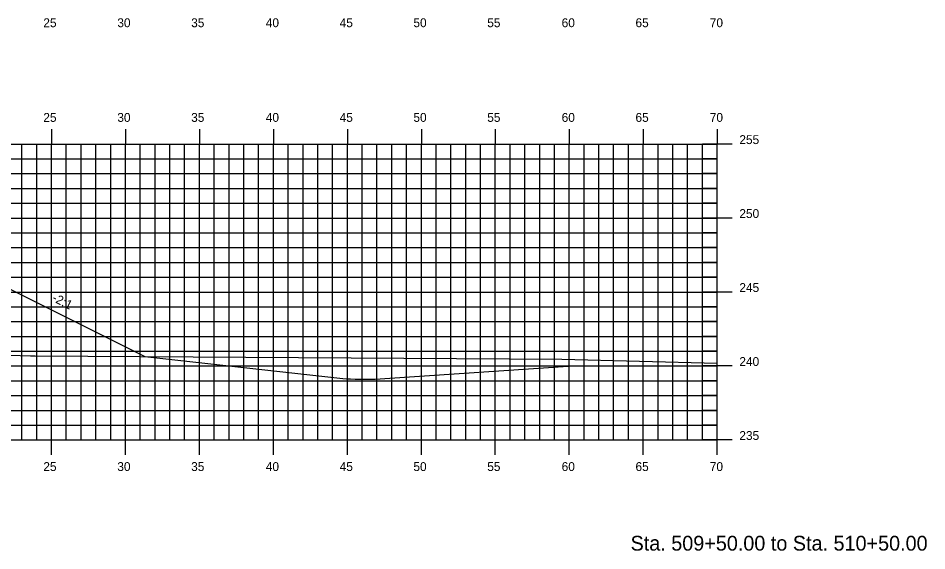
# Model space of a CAD drawing. Extents: x 1170543 to 1177585, y 609599 to 610623.
# Drawn here: x 1172423.3 to 1172484.7, y 610270.3 to 610306.3 of the extents above; entities that cross this region are included whole.
import ezdxf

# ---------------------------------------------------------------- set-up
doc = ezdxf.new("R2010")
doc.units = 0
for name, color, linetype in [('ANNOTATION', 7, 'Continuous'), ('D_Roadway_Centerline', 7, 'Continuous'), ('D_Roadway_Edge_Pavement', 7, 'Continuous'), ('H_V ANNOTATION', 7, 'Continuous'), ('MAJOR', 7, 'Continuous'), ('MINOR', 7, 'Continuous'), ('S_Roadway_Centerline', 7, 'Continuous')]:
    doc.layers.add(name, color=color, linetype=linetype)

msp = doc.modelspace()

# ---------------------------------------------------------------- linework, layer by layer
at = {"layer": 'D_Roadway_Centerline'}
msp.add_lwpolyline([(1172382.176, 610291.056), (1172386.743, 610290.875), (1172387.337, 610290.851), (1172390.392, 610290.731), (1172390.428, 610290.729), (1172395.154, 610290.546), (1172395.785, 610290.521), (1172408.22, 610290.035), (1172416.521, 610289.722), (1172416.521, 610289.722), (1172419.505, 610289.607), (1172423.005, 610287.857), (1172423.005, 610287.857), (1172431.831, 610283.444)], dxfattribs=at)
at = {"layer": 'D_Roadway_Edge_Pavement'}
msp.add_lwpolyline([(1172431.831, 610283.444), (1172445.213, 610281.963), (1172445.459, 610281.94), (1172445.737, 610281.922), (1172446.043, 610281.909), (1172446.372, 610281.903), (1172446.711, 610281.902), (1172447.056, 610281.907), (1172447.399, 610281.917), (1172447.731, 610281.932), (1172448.047, 610281.951), (1172460.788, 610282.801)], dxfattribs=at)
at = {"layer": 'MAJOR'}
for p, q in [((1172425.524, 610298.803), (1172425.524, 610297.801)), ((1172430.524, 610298.803), (1172430.524, 610297.801)), ((1172435.524, 610298.803), (1172435.524, 610297.801)), ((1172440.524, 610298.803), (1172440.524, 610297.801)), ((1172445.524, 610298.803), (1172445.524, 610297.801)), ((1172450.524, 610298.803), (1172450.524, 610297.801)), ((1172455.524, 610298.803), (1172455.524, 610297.801)), ((1172460.524, 610298.803), (1172460.524, 610297.801)), ((1172465.524, 610298.803), (1172465.524, 610297.801)), ((1172470.524, 610298.803), (1172470.524, 610297.801)), ((1172330.524, 610297.801), (1172470.524, 610297.801)), ((1172330.524, 610297.801), (1172470.524, 610297.801)), ((1172425.524, 610277.801), (1172425.524, 610297.801)), ((1172430.524, 610277.801), (1172430.524, 610297.801)), ((1172435.524, 610277.801), (1172435.524, 610297.801)), ((1172440.524, 610277.801), (1172440.524, 610297.801)), ((1172445.524, 610277.801), (1172445.524, 610297.801)), ((1172450.524, 610277.801), (1172450.524, 610297.801)), ((1172455.524, 610277.801), (1172455.524, 610297.801)), ((1172460.524, 610277.801), (1172460.524, 610297.801)), ((1172465.524, 610277.801), (1172465.524, 610297.801)), ((1172471.526, 610297.801), (1172469.522, 610297.801)), ((1172470.524, 610277.801), (1172470.524, 610297.801)), ((1172470.524, 610277.801), (1172470.524, 610297.801)), ((1172330.524, 610292.801), (1172470.524, 610292.801)), ((1172471.526, 610292.801), (1172469.522, 610292.801)), ((1172330.524, 610287.801), (1172470.524, 610287.801)), ((1172471.526, 610287.801), (1172469.522, 610287.801)), ((1172330.524, 610282.801), (1172470.524, 610282.801)), ((1172471.526, 610282.801), (1172469.522, 610282.801)), ((1172330.524, 610277.801), (1172470.524, 610277.801)), ((1172330.524, 610277.801), (1172470.524, 610277.801)), ((1172425.524, 610276.799), (1172425.524, 610277.801)), ((1172430.524, 610276.799), (1172430.524, 610277.801)), ((1172435.524, 610276.799), (1172435.524, 610277.801)), ((1172440.524, 610276.799), (1172440.524, 610277.801)), ((1172445.524, 610276.799), (1172445.524, 610277.801)), ((1172450.524, 610276.799), (1172450.524, 610277.801)), ((1172455.524, 610276.799), (1172455.524, 610277.801)), ((1172460.524, 610276.799), (1172460.524, 610277.801)), ((1172465.524, 610276.799), (1172465.524, 610277.801)), ((1172471.526, 610277.801), (1172469.522, 610277.801)), ((1172470.524, 610276.799), (1172470.524, 610277.801))]:
    msp.add_line(p, q, dxfattribs=at)
at = {"layer": 'MINOR'}
for p, q in [((1172423.524, 610277.801), (1172423.524, 610297.801)), ((1172424.524, 610277.801), (1172424.524, 610297.801)), ((1172426.524, 610277.801), (1172426.524, 610297.801)), ((1172427.524, 610277.801), (1172427.524, 610297.801)), ((1172428.524, 610277.801), (1172428.524, 610297.801)), ((1172429.524, 610277.801), (1172429.524, 610297.801)), ((1172431.524, 610277.801), (1172431.524, 610297.801)), ((1172432.524, 610277.801), (1172432.524, 610297.801)), ((1172433.524, 610277.801), (1172433.524, 610297.801)), ((1172434.524, 610277.801), (1172434.524, 610297.801)), ((1172436.524, 610277.801), (1172436.524, 610297.801)), ((1172437.524, 610277.801), (1172437.524, 610297.801)), ((1172438.524, 610277.801), (1172438.524, 610297.801)), ((1172439.524, 610277.801), (1172439.524, 610297.801)), ((1172441.524, 610277.801), (1172441.524, 610297.801)), ((1172442.524, 610277.801), (1172442.524, 610297.801)), ((1172443.524, 610277.801), (1172443.524, 610297.801)), ((1172444.524, 610277.801), (1172444.524, 610297.801)), ((1172446.524, 610277.801), (1172446.524, 610297.801)), ((1172447.524, 610277.801), (1172447.524, 610297.801)), ((1172448.524, 610277.801), (1172448.524, 610297.801)), ((1172449.524, 610277.801), (1172449.524, 610297.801)), ((1172451.524, 610277.801), (1172451.524, 610297.801)), ((1172452.524, 610277.801), (1172452.524, 610297.801)), ((1172453.524, 610277.801), (1172453.524, 610297.801)), ((1172454.524, 610277.801), (1172454.524, 610297.801)), ((1172456.524, 610277.801), (1172456.524, 610297.801)), ((1172457.524, 610277.801), (1172457.524, 610297.801)), ((1172458.524, 610277.801), (1172458.524, 610297.801)), ((1172459.524, 610277.801), (1172459.524, 610297.801)), ((1172461.524, 610277.801), (1172461.524, 610297.801)), ((1172462.524, 610277.801), (1172462.524, 610297.801)), ((1172463.524, 610277.801), (1172463.524, 610297.801)), ((1172464.524, 610277.801), (1172464.524, 610297.801)), ((1172466.524, 610277.801), (1172466.524, 610297.801)), ((1172467.524, 610277.801), (1172467.524, 610297.801)), ((1172468.524, 610277.801), (1172468.524, 610297.801)), ((1172469.524, 610277.801), (1172469.524, 610297.801)), ((1172330.524, 610296.801), (1172470.524, 610296.801)), ((1172470.524, 610296.801), (1172469.522, 610296.801)), ((1172330.524, 610295.801), (1172470.524, 610295.801)), ((1172470.524, 610295.801), (1172469.522, 610295.801)), ((1172330.524, 610294.801), (1172470.524, 610294.801)), ((1172470.524, 610294.801), (1172469.522, 610294.801)), ((1172330.524, 610293.801), (1172470.524, 610293.801)), ((1172470.524, 610293.801), (1172469.522, 610293.801)), ((1172330.524, 610291.801), (1172470.524, 610291.801)), ((1172470.524, 610291.801), (1172469.522, 610291.801)), ((1172330.524, 610290.801), (1172470.524, 610290.801)), ((1172470.524, 610290.801), (1172469.522, 610290.801)), ((1172330.524, 610289.801), (1172470.524, 610289.801)), ((1172470.524, 610289.801), (1172469.522, 610289.801)), ((1172330.524, 610288.801), (1172470.524, 610288.801)), ((1172470.524, 610288.801), (1172469.522, 610288.801)), ((1172330.524, 610286.801), (1172470.524, 610286.801)), ((1172470.524, 610286.801), (1172469.522, 610286.801)), ((1172330.524, 610285.801), (1172470.524, 610285.801)), ((1172470.524, 610285.801), (1172469.522, 610285.801)), ((1172330.524, 610284.801), (1172470.524, 610284.801)), ((1172470.524, 610284.801), (1172469.522, 610284.801)), ((1172330.524, 610283.801), (1172470.524, 610283.801)), ((1172470.524, 610283.801), (1172469.522, 610283.801)), ((1172330.524, 610281.801), (1172470.524, 610281.801)), ((1172470.524, 610281.801), (1172469.522, 610281.801)), ((1172330.524, 610280.801), (1172470.524, 610280.801)), ((1172470.524, 610280.801), (1172469.522, 610280.801)), ((1172330.524, 610279.801), (1172470.524, 610279.801)), ((1172470.524, 610279.801), (1172469.522, 610279.801)), ((1172330.524, 610278.801), (1172470.524, 610278.801)), ((1172470.524, 610278.801), (1172469.522, 610278.801))]:
    msp.add_line(p, q, dxfattribs=at)
at = {"layer": 'S_Roadway_Centerline'}
msp.add_lwpolyline([(1172422.715, 610283.529), (1172424.101, 610283.495), (1172424.418, 610283.491), (1172460.027, 610283.263), (1172470.524, 610282.989)], dxfattribs=at)

# ---------------------------------------------------------------- texts
at = {"layer": 'ANNOTATION'}
msp.add_text('-2:1', height=0.6, rotation=333.35522, dxfattribs=at).set_placement((1172425.515, 610287.219))
at = {"layer": 'H_V ANNOTATION'}
for s, height, p in [('25', 0.6, (1172424.97, 610305.701)), ('30', 0.6, (1172429.972, 610305.701)), ('35', 0.6, (1172434.964, 610305.701)), ('40', 0.6, (1172440.01, 610305.701)), ('45', 0.6, (1172445.002, 610305.701)), ('50', 0.6, (1172449.988, 610305.701)), ('55', 0.6, (1172454.98, 610305.701)), ('60', 0.6, (1172460.01, 610305.701)), ('65', 0.6, (1172465.002, 610305.701)), ('70', 0.6, (1172470.026, 610305.701)), ('25', 0.6, (1172424.97, 610299.301)), ('30', 0.6, (1172429.972, 610299.301)), ('35', 0.6, (1172434.964, 610299.301)), ('40', 0.6, (1172440.01, 610299.301)), ('45', 0.6, (1172445.002, 610299.301)), ('50', 0.6, (1172449.988, 610299.301)), ('55', 0.6, (1172454.98, 610299.301)), ('60', 0.6, (1172460.01, 610299.301)), ('65', 0.6, (1172465.002, 610299.301)), ('70', 0.6, (1172470.026, 610299.301)), ('255', 0.6, (1172472.024, 610297.801)), ('250', 0.6, (1172472.024, 610292.801)), ('245', 0.6, (1172472.024, 610287.801)), ('240', 0.6, (1172472.024, 610282.801)), ('235', 0.6, (1172472.024, 610277.801)), ('25', 0.6, (1172424.97, 610275.701)), ('30', 0.6, (1172429.972, 610275.701)), ('35', 0.6, (1172434.964, 610275.701)), ('40', 0.6, (1172440.01, 610275.701)), ('45', 0.6, (1172445.002, 610275.701)), ('50', 0.6, (1172449.988, 610275.701)), ('55', 0.6, (1172454.98, 610275.701)), ('60', 0.6, (1172460.01, 610275.701)), ('65', 0.6, (1172465.002, 610275.701)), ('70', 0.6, (1172470.026, 610275.701)), ('Sta. 509+50.00 to Sta. 510+50.00', 1.0002, (1172464.669, 610270.321))]:
    msp.add_text(s, height=height, dxfattribs=at).set_placement(p)

doc.saveas('drawing.dxf')
